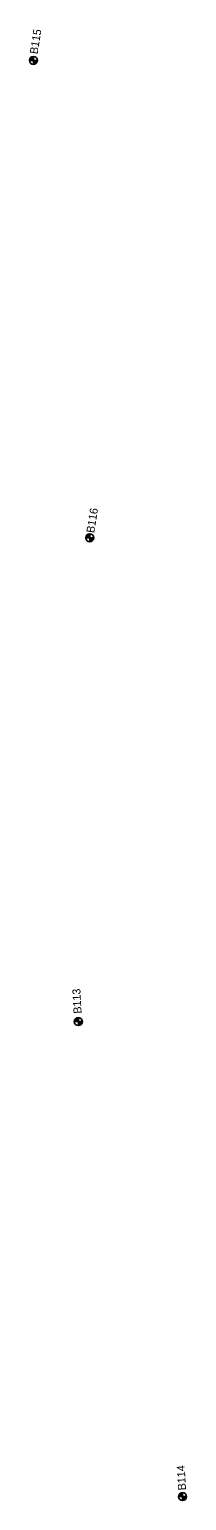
# Model space of a CAD drawing. Extents: x 311409 to 379449, y 121539 to 224848.
# Drawn here: x 355125 to 355322, y 190786 to 192625 of the extents above; entities that cross this region are included whole.
import ezdxf

# ---------------------------------------------------------------- set-up
doc = ezdxf.new("R2010")
doc.units = 0
for name, color, linetype in [('E_SOIL_BORE1 [KAPUR_CADDS_LEVELS]', 7, 'Continuous'), ('E_SOIL_BORE2 [KAPUR_CADDS_LEVELS]', 7, 'Continuous'), ('P_MARK', 7, 'Continuous')]:
    doc.layers.add(name, color=color, linetype=linetype)

msp = doc.modelspace()

# ---------------------------------------------------------------- linework, layer by layer
at = {"layer": 'P_MARK'}
for p, q in [((355130.2, 192590.9), (355130.2, 192580.9)), ((355125.2, 192585.9), (355135.2, 192585.9)), ((355195.5, 191989.3), (355205.5, 191989.3)), ((355200.5, 191994.3), (355200.5, 191984.3)), ((355181.3, 191384.7), (355191.3, 191384.7)), ((355186.3, 191389.7), (355186.3, 191379.7)), ((355311.6, 190791.1), (355321.6, 190791.1)), ((355316.6, 190796.1), (355316.6, 190786.1))]:
    msp.add_line(p, q, dxfattribs=at)
for centre in [(355130.2, 192585.9), (355200.5, 191989.3), (355186.3, 191384.7), (355316.6, 190791.1)]:
    msp.add_circle(centre, 5, dxfattribs=at)
for centre, radius, start, end in [((355130.2, 192585.9), 4.5, 89.9869, 179.9869), ((355130.2, 192585.9), 4, 89.9869, 179.9869), ((355130.2, 192585.9), 3.5, 89.9869, 179.9869), ((355130.2, 192585.9), 3, 89.9869, 179.9869), ((355130.2, 192585.9), 2.5, 89.9869, 179.9869), ((355130.2, 192585.9), 2, 89.9869, 179.9869), ((355130.2, 192585.9), 1.5, 89.9869, 179.9869), ((355130.2, 192585.9), 1, 89.9869, 179.9869), ((355130.2, 192585.9), 0.5, 89.9869, 179.9869), ((355130.2, 192585.9), 4.5, 269.9869, 359.9869), ((355130.2, 192585.9), 4, 269.9869, 359.9869), ((355130.2, 192585.9), 3.5, 269.9869, 359.9869), ((355130.2, 192585.9), 3, 269.9869, 359.9869), ((355130.2, 192585.9), 2.5, 269.9869, 359.9869), ((355130.2, 192585.9), 2, 269.9869, 359.9869), ((355130.2, 192585.9), 1.5, 269.9869, 359.9869), ((355130.2, 192585.9), 1, 269.9869, 359.9869), ((355130.2, 192585.9), 0.5, 269.9869, 359.9869), ((355200.5, 191989.3), 4.5, 89.9869, 179.9869), ((355200.5, 191989.3), 4, 89.9869, 179.9869), ((355200.5, 191989.3), 3.5, 89.9869, 179.9869), ((355200.5, 191989.3), 3, 89.9869, 179.9869), ((355200.5, 191989.3), 2.5, 89.9869, 179.9869), ((355200.5, 191989.3), 2, 89.9869, 179.9869), ((355200.5, 191989.3), 1.5, 89.9869, 179.9869), ((355200.5, 191989.3), 1, 89.9869, 179.9869), ((355200.5, 191989.3), 0.5, 89.9869, 179.9869), ((355200.5, 191989.3), 4.5, 269.9869, 359.9869), ((355200.5, 191989.3), 4, 269.9869, 359.9869), ((355200.5, 191989.3), 3.5, 269.9869, 359.9869), ((355200.5, 191989.3), 3, 269.9869, 359.9869), ((355200.5, 191989.3), 2.5, 269.9869, 359.9869), ((355200.5, 191989.3), 2, 269.9869, 359.9869), ((355200.5, 191989.3), 1.5, 269.9869, 359.9869), ((355200.5, 191989.3), 1, 269.9869, 359.9869), ((355200.5, 191989.3), 0.5, 269.9869, 359.9869), ((355186.3, 191384.7), 4.5, 89.9869, 179.9869), ((355186.3, 191384.7), 4, 89.9869, 179.9869), ((355186.3, 191384.7), 3.5, 89.9869, 179.9869), ((355186.3, 191384.7), 3, 89.9869, 179.9869), ((355186.3, 191384.7), 2.5, 89.9869, 179.9869), ((355186.3, 191384.7), 2, 89.9869, 179.9869), ((355186.3, 191384.7), 1.5, 89.9869, 179.9869), ((355186.3, 191384.7), 1, 89.9869, 179.9869), ((355186.3, 191384.7), 0.5, 89.9869, 179.9869), ((355186.3, 191384.7), 4.5, 269.9869, 359.9869), ((355186.3, 191384.7), 4, 269.9869, 359.9869), ((355186.3, 191384.7), 3.5, 269.9869, 359.9869), ((355186.3, 191384.7), 3, 269.9869, 359.9869), ((355186.3, 191384.7), 2.5, 269.9869, 359.9869), ((355186.3, 191384.7), 2, 269.9869, 359.9869), ((355186.3, 191384.7), 1.5, 269.9869, 359.9869), ((355186.3, 191384.7), 1, 269.9869, 359.9869), ((355186.3, 191384.7), 0.5, 269.9869, 359.9869), ((355316.6, 190791.1), 4.5, 89.9869, 179.9869), ((355316.6, 190791.1), 4, 89.9869, 179.9869), ((355316.6, 190791.1), 3.5, 89.9869, 179.9869), ((355316.6, 190791.1), 3, 89.9869, 179.9869), ((355316.6, 190791.1), 2.5, 89.9869, 179.9869), ((355316.6, 190791.1), 2, 89.9869, 179.9869), ((355316.6, 190791.1), 1.5, 89.9869, 179.9869), ((355316.6, 190791.1), 1, 89.9869, 179.9869), ((355316.6, 190791.1), 0.5, 89.9869, 179.9869), ((355316.6, 190791.1), 4.5, 269.9869, 359.9869), ((355316.6, 190791.1), 4, 269.9869, 359.9869), ((355316.6, 190791.1), 3.5, 269.9869, 359.9869), ((355316.6, 190791.1), 3, 269.9869, 359.9869), ((355316.6, 190791.1), 2.5, 269.9869, 359.9869), ((355316.6, 190791.1), 2, 269.9869, 359.9869), ((355316.6, 190791.1), 1.5, 269.9869, 359.9869), ((355316.6, 190791.1), 1, 269.9869, 359.9869), ((355316.6, 190791.1), 0.5, 269.9869, 359.9869)]:
    msp.add_arc(centre, radius, start, end, dxfattribs=at)

# ---------------------------------------------------------------- texts
at = {"layer": 'E_SOIL_BORE1 [KAPUR_CADDS_LEVELS]'}
for s, rotation, p in [('B115', 80.9358, (355135.3, 192593.3)), ('B114', 93.0065, (355320.9, 190799.2))]:
    msp.add_text(s, height=10, rotation=rotation, dxfattribs=at).set_placement(p)
at = {"layer": 'E_SOIL_BORE2 [KAPUR_CADDS_LEVELS]'}
for s, rotation, p in [('B116', 80.9358, (355206.1, 191994.8)), ('B113', 93.0065, (355190.4, 191394.9))]:
    msp.add_text(s, height=10, rotation=rotation, dxfattribs=at).set_placement(p)

doc.saveas('drawing.dxf')
